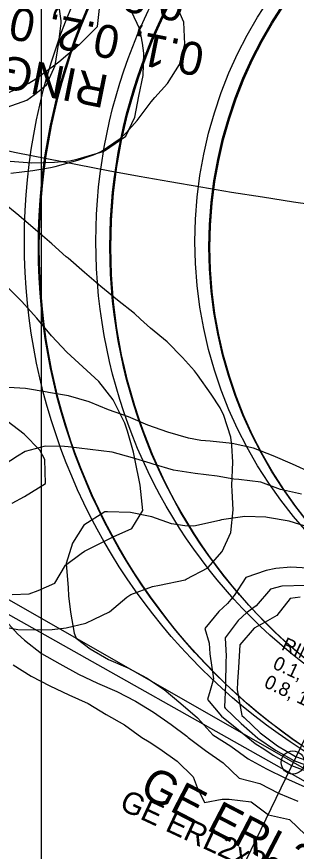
# Model space of a CAD drawing. Extents: x 1638506 to 1658005, y 834807 to 846788.
# Drawn here: x 1640408.1 to 1640509.7, y 842395.5 to 842698.3 of the extents above; entities that cross this region are included whole.
import ezdxf

# ---------------------------------------------------------------- set-up
doc = ezdxf.new("R2010")
doc.units = 0
for name, color, linetype in [('Default', 7, 'Continuous'), ('Old_Level_1', 7, 'Continuous'), ('Old_Level_2', 7, 'Continuous'), ('Old_Level_4', 7, 'Continuous'), ('Scratch_Level_0', 7, 'Continuous')]:
    doc.layers.add(name, color=color, linetype=linetype)

msp = doc.modelspace()

# ---------------------------------------------------------------- linework, layer by layer
at = {"layer": 'Default'}
for p, q in [((1640417.09, 842265.25), (1640417.09, 842913.91)), ((1640314.09, 842532.64), (1640637.56, 842350.59))]:
    msp.add_line(p, q, dxfattribs=at)
at = {"layer": 'Old_Level_1'}
for points in [[(1640404.66, 842665.52), (1640411.74, 842668.04), (1640414.41, 842669.97), (1640418.93, 842673.57), (1640422, 842680.59), (1640423.26, 842688.27), (1640424.27, 842696.05), (1640424.19, 842696.83), (1640423.11, 842704.61), (1640420.79, 842709.85), (1640419.19, 842714.18), (1640417.86, 842722.8), (1640417.54, 842723.3), (1640412.19, 842730.97), (1640408.78, 842734.25), (1640406.01, 842736.34)], [(1640405.68, 842645.97), (1640413.58, 842645.32), (1640421.81, 842645.56), (1640427.34, 842646.09), (1640430.39, 842646.75), (1640439.52, 842649.47), (1640440, 842649.62), (1640447.69, 842654.96), (1640451, 842661.9), (1640452.46, 842669.5), (1640454.08, 842677.06), (1640454.34, 842685.1), (1640453.81, 842688.73), (1640452.87, 842693.78), (1640449.83, 842700.18)], [(1640515.2, 842532.77), (1640508.27, 842536), (1640501.24, 842539.03), (1640494.08, 842541.77), (1640486.4, 842543.41), (1640478.37, 842544.28), (1640475.03, 842544.58), (1640470.47, 842545.44), (1640463.02, 842547.57), (1640455.75, 842550.09), (1640448.73, 842553.13), (1640441.49, 842555.71), (1640434.41, 842558.62), (1640426.95, 842560.73), (1640419.58, 842561.99), (1640419.13, 842562.06), (1640411.32, 842563.4), (1640403.1, 842563.88)], [(1640511.62, 842525.09), (1640503.99, 842526.83), (1640496.78, 842529.45), (1640488.77, 842530.38), (1640486.96, 842530.57), (1640480.9, 842531.6), (1640472.92, 842532.59), (1640465.06, 842533.85), (1640457.63, 842536.02), (1640456.55, 842536.31), (1640450.21, 842538.21), (1640442.77, 842540.33), (1640434.8, 842541.35), (1640426.76, 842542.22), (1640425.47, 842542.37), (1640418.45, 842542.49), (1640411.17, 842540.6), (1640408.34, 842538.91), (1640403.52, 842535.72)], [(1640514.44, 842513.03), (1640507.06, 842515.3), (1640499.22, 842516.6), (1640498.63, 842516.69), (1640490.95, 842516.95), (1640482.53, 842515.76), (1640481.82, 842515.48), (1640472.45, 842513.48), (1640469.14, 842513.56), (1640464.37, 842514.27), (1640457.13, 842516.83), (1640449.46, 842518.49), (1640441.12, 842518.71), (1640440.13, 842518.65), (1640432.44, 842513.8), (1640428.37, 842507.25), (1640426.09, 842499.87), (1640426.75, 842491.12), (1640426.89, 842488.2), (1640427.57, 842482.3), (1640429, 842474.6), (1640429.67, 842472.88), (1640434.79, 842468.93), (1640441.46, 842465.13), (1640448.45, 842462.02), (1640455.2, 842458.4), (1640461.69, 842454.21), (1640467.76, 842449.12), (1640473.78, 842443.92), (1640473.87, 842443.83), (1640479.33, 842437.73), (1640485.84, 842433.59), (1640492.15, 842429.01), (1640498.91, 842425.41), (1640505.77, 842422.02), (1640512.77, 842418.94)], [(1640515.91, 842498.08), (1640507.73, 842498.64), (1640502.26, 842498.12), (1640498.69, 842497.35), (1640491.29, 842494.79), (1640487.05, 842488.33), (1640484.68, 842485.4), (1640481.52, 842482.47), (1640476.47, 842476.38), (1640477.99, 842471.07), (1640478.22, 842467.13), (1640479.54, 842458.07), (1640478.4, 842453.85), (1640477.39, 842450.63), (1640482.5, 842444.54), (1640488.65, 842439.62), (1640494.77, 842434.65), (1640498.24, 842432.47), (1640501.24, 842430.41), (1640507.89, 842426.57), (1640515.1, 842423.94)], [(1640513.08, 842492), (1640504.49, 842491.7), (1640500.34, 842490.57), (1640495.16, 842484.55), (1640491.56, 842482.06), (1640488.52, 842479.2), (1640483.89, 842472.92), (1640484.21, 842466.31), (1640484.09, 842464.39), (1640483.92, 842456.03), (1640483.55, 842447.76), (1640483.84, 842447.41), (1640489.67, 842441.81), (1640495.66, 842436.54), (1640502.07, 842432.2), (1640508.75, 842428.43), (1640515.94, 842425.74)], [(1640511.07, 842487.69), (1640507.5, 842487.23), (1640502.61, 842481.08), (1640498.4, 842478.63), (1640494.41, 842476.46), (1640489.15, 842470.47), (1640488.69, 842462.24), (1640488.28, 842456.94), (1640488.23, 842454.02), (1640489.84, 842444.82), (1640490.69, 842444), (1640496.54, 842438.44), (1640502.82, 842433.8), (1640509.43, 842429.87), (1640516.69, 842427.34)], [(1640405.23, 842477.95), (1640408.35, 842474.38), (1640410.93, 842472.06), (1640417.14, 842467.27), (1640423.8, 842463.46), (1640430.5, 842459.73), (1640437.43, 842456.48), (1640444.49, 842453.52), (1640451.29, 842450.01), (1640457.85, 842445.98), (1640464.19, 842441.46), (1640469.88, 842437.25), (1640470.42, 842436.73), (1640476.7, 842432.1), (1640483.06, 842427.64), (1640488.91, 842422.08), (1640496.44, 842420.12), (1640503.25, 842416.62), (1640510.3, 842413.65)], [(1640406.77, 842463.14), (1640413.31, 842459.07), (1640420.1, 842455.53), (1640427.02, 842452.26), (1640434.01, 842449.16), (1640440.59, 842445.17), (1640447.25, 842441.34), (1640453.59, 842436.84), (1640456.26, 842435.16), (1640460.09, 842432.67), (1640466.44, 842428.18), (1640472.25, 842422.54), (1640473.61, 842418.63), (1640476.35, 842413.25), (1640482.75, 842414.37), (1640485.31, 842414.35), (1640493.33, 842413.46), (1640499.55, 842408.7), (1640507.2, 842407), (1640513.04, 842401.41), (1640514.7, 842399.47), (1640517.95, 842393.85)]]:
    msp.add_lwpolyline(points, dxfattribs=at)
for centre, radius in [((1640635.3, 842614.58), 219), ((1640635.3, 842614.58), 193), ((1640635.3, 842614.58), 157), ((1640508.42, 842427.72), 4.21)]:
    msp.add_circle(centre, radius, dxfattribs=at)
at = {"layer": 'Old_Level_2'}
for p, q in [((1640570.5, 842555.69), (1640460.25, 842328.04)), ((1640394.38, 842493.02), (1640843.22, 842236.75))]:
    msp.add_line(p, q, dxfattribs=at)
msp.add_arc((1640787.74, 844492.39), 1882, 251.76578, 273.94492, dxfattribs=at)
at = {"layer": 'Old_Level_4'}
for radius in [219, 193, 157]:
    msp.add_circle((1640629.86, 842616.81), radius, dxfattribs=at)
at = {"layer": 'Scratch_Level_0'}
for points in [[(1640403.87, 842670.27), (1640412.45, 842674.19), (1640415.07, 842675.82), (1640421.5, 842680.48), (1640423.37, 842681.97), (1640430.84, 842688.2), (1640430.92, 842688.27), (1640437.39, 842694.78), (1640438.29, 842702.4), (1640434.99, 842709.01), (1640434.06, 842711.04), (1640430.09, 842719.63), (1640429.58, 842721.02), (1640427.89, 842727.87), (1640428.92, 842735.47), (1640425.82, 842741.29), (1640424.04, 842744.24), (1640419.43, 842748.36), (1640412.6, 842753.2), (1640406.74, 842755.49)], [(1640405.95, 842641.59), (1640413.94, 842642.52), (1640420.34, 842643.57), (1640422.04, 842644.01), (1640430.3, 842646.34), (1640436.01, 842648.25), (1640438.73, 842649.49), (1640445.7, 842654.12), (1640447.88, 842656.25), (1640451.89, 842660.68), (1640456.91, 842667.48), (1640458.23, 842669.03), (1640462.83, 842674.1), (1640467.29, 842681.02), (1640469.17, 842688.44), (1640468.8, 842696.32), (1640465.27, 842704.38)], [(1640486.74, 842519.4), (1640486.32, 842526.24), (1640486.26, 842528.27), (1640486.59, 842536.72), (1640486.24, 842542.69), (1640485.87, 842545.71), (1640483.33, 842553.69), (1640481.98, 842556.36), (1640478.72, 842561.41), (1640473.73, 842568.4), (1640472.68, 842569.81), (1640468.35, 842574.63), (1640462.7, 842580.35), (1640456.66, 842585.33), (1640453.09, 842588.61), (1640450.83, 842590.69), (1640444.69, 842595.47), (1640438.68, 842600.5), (1640432.68, 842605.53), (1640426.74, 842610.7), (1640426.11, 842611.24), (1640420.83, 842615.93), (1640414.86, 842621.02), (1640408.9, 842626.15), (1640402.86, 842631.1)], [(1640452.98, 842528.32), (1640452.96, 842528.41), (1640451.03, 842537.95), (1640450.5, 842540.28), (1640448.4, 842547.94), (1640447.38, 842550.85), (1640443.13, 842559.27), (1640443.11, 842559.31), (1640437.96, 842565.92), (1640432.13, 842571.28), (1640426.33, 842576.64), (1640426.3, 842576.67), (1640420.75, 842582.58), (1640415.45, 842588.97), (1640412.03, 842592.69), (1640409.93, 842594.94), (1640404.3, 842600.69)], [(1640418.28, 842537.72), (1640416.45, 842541.09), (1640410.79, 842546.81), (1640404.63, 842551.54)], [(1640406.44, 842521.82), (1640410.95, 842524.29), (1640418.49, 842528.99), (1640418.28, 842537.72)], [(1640406.43, 842488.62), (1640412.6, 842488.95), (1640415.84, 842490.13), (1640421.9, 842492.74), (1640425.84, 842499.31), (1640431.45, 842503.59), (1640432.71, 842504.36), (1640441.19, 842508.58), (1640443.18, 842509.58), (1640449.89, 842512.68), (1640453.96, 842519.19), (1640452.98, 842528.32)], [(1640402.08, 842477.17), (1640408.49, 842475.99), (1640417.05, 842475.86), (1640420.95, 842475.99), (1640426.05, 842476.61), (1640433.21, 842478.24), (1640436.27, 842479.67), (1640441.85, 842482.37), (1640448.09, 842487.76), (1640449.54, 842488.63), (1640457.42, 842491.53), (1640459.96, 842492.09), (1640469.24, 842494.01), (1640469.7, 842494.25), (1640477.5, 842498.34), (1640482.71, 842504.25), (1640485.89, 842511.22), (1640486.74, 842519.4)]]:
    msp.add_lwpolyline(points, dxfattribs=at)
for radius in [219, 193, 157]:
    msp.add_circle((1640634.95, 842614.89), radius, dxfattribs=at)

# ---------------------------------------------------------------- texts
at = {"layer": 'Old_Level_1'}
for s, height, p in [('RING VALUES', 5, (1640503.95, 842468.81)), ('0.1, 0.2, 0.4,', 5, (1640500.78, 842462.02)), ('0.8, 1.0, 1.2', 5, (1640497.61, 842455.22)), ('GE ERL2x23B340', 8, (1640444.98, 842410.94))]:
    msp.add_text(s, height=height, rotation=335, dxfattribs=at).set_placement(p)
at = {"layer": 'Scratch_Level_0'}
for s, rotation, p in [('0.8, 1.0, 1.2', 168.7284, (1640470.05, 842708)), ('0.1, 0.2, 0.4,', 168.7284, (1640476.9, 842688.28)), ('RING VALUES', 168.7284, (1640442.03, 842676.88)), ('GE ERL2x23C340', 332.5519, (1640452.16, 842416.2))]:
    msp.add_text(s, height=12, rotation=rotation, dxfattribs=at).set_placement(p)

doc.saveas('drawing.dxf')
